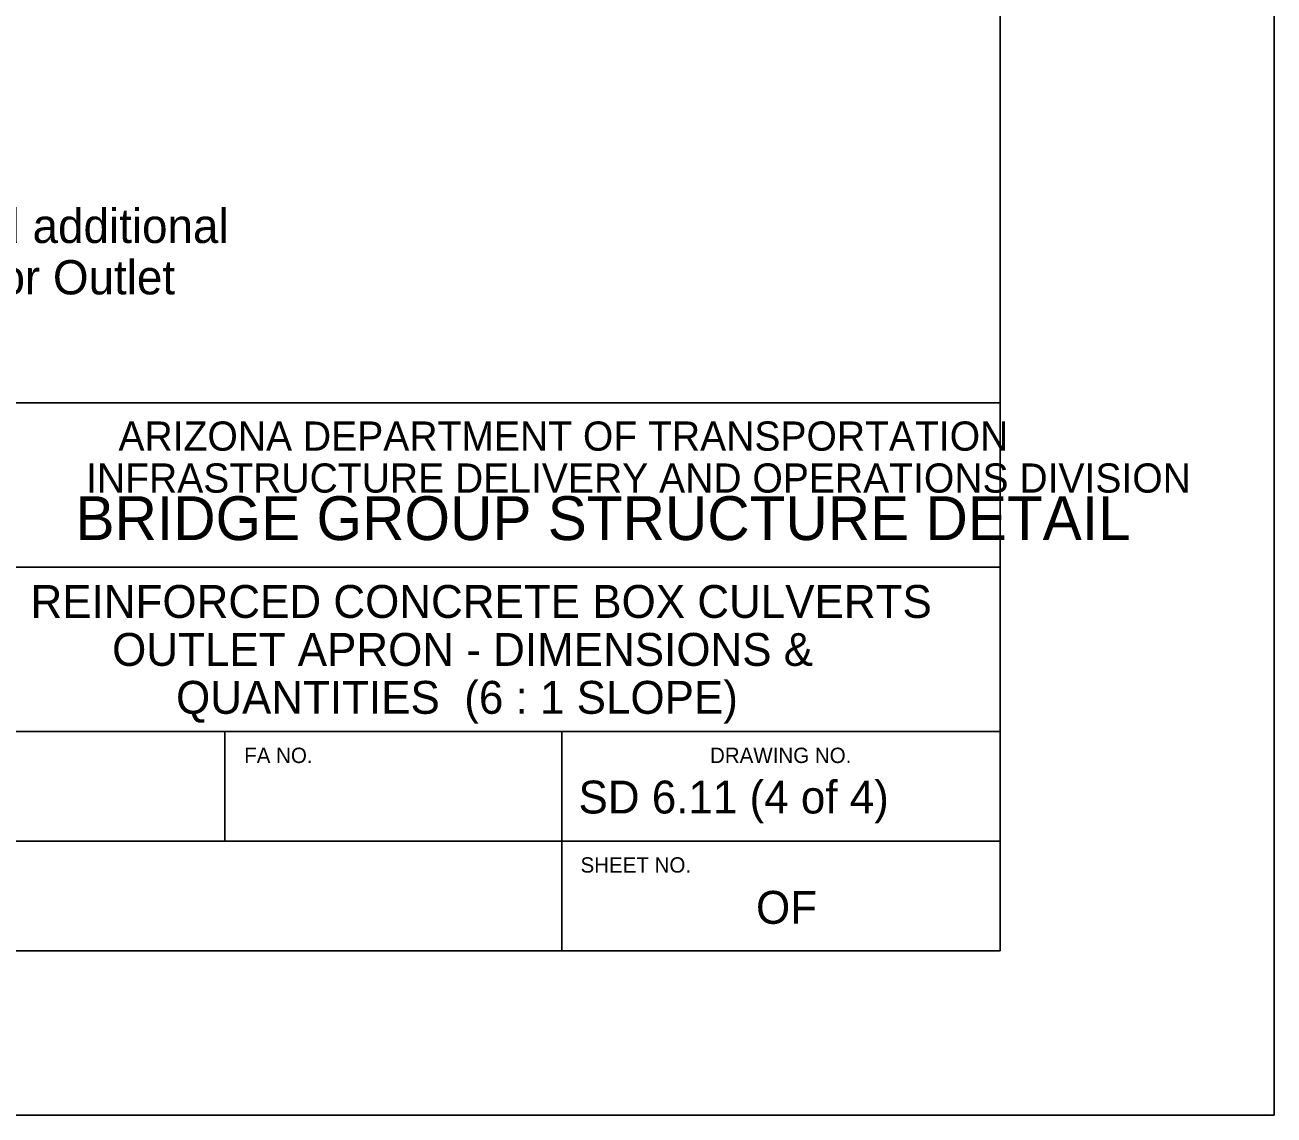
# Model space of a CAD drawing. Extents: x -0.08 to 2.83, y -0.03 to 1.92.
# Drawn here: x 2.3584 to 2.8333, y 0 to 0.4144 of the extents above; entities that cross this region are included whole.
import ezdxf

# ---------------------------------------------------------------- set-up
doc = ezdxf.new("R2010")
doc.units = 0
for name, color, linetype in [('57', 7, 'Continuous'), ('62', 7, 'Continuous'), ('63', 7, 'Continuous')]:
    doc.layers.add(name, color=color, linetype=linetype)

msp = doc.modelspace()

# ---------------------------------------------------------------- linework, layer by layer
at = {"layer": '63'}
for p, q in [((2.8333333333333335, 1.8333333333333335), (2.8333333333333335, 0)), ((2.729175, 0.270775), (2.073866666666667, 0.270775)), ((2.5728416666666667, 0.270775), (2.5728416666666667, 0.270775)), ((2.073866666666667, 0.20827500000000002), (2.729175, 0.20827500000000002)), ((2.073866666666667, 0.14577500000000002), (2.729175, 0.14577500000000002)), ((2.434346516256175, 0.10410833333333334), (2.434346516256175, 0.14577500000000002)), ((2.073866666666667, 0.10410833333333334), (2.5625083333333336, 0.10410833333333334)), ((2.5625083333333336, 0.10410833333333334), (2.5625083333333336, 0.06244166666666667)), ((2.729175, 0.06244166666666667), (2.729175, 0.10410833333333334)), ((2.073866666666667, 0.06244166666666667), (2.729175, 0.06244166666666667)), ((2.8333333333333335, 0), (0, 0)), ((2.83, 0.00032500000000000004), (2.83, 0.00032500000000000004))]:
    msp.add_line(p, q, dxfattribs=at)
msp.add_lwpolyline([(0.16667500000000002, 0.06244166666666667), (0.16667500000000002, 1.770775), (2.729175, 1.770775), (2.729175, 0.10410833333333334), (2.5625083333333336, 0.10410833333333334), (2.5625083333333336, 0.14577500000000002), (2.073866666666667, 0.14577500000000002), (2.073866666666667, 0.06244166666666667)], close=True, dxfattribs=at)

# ---------------------------------------------------------------- texts
at = {"layer": '57'}
for s, p in [('For General Notes, Dimensions, and additional', (2.073866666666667, 0.3315448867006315)), ('For General Notes, Dimensions, and additional', (2.073866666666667, 0.3315448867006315)), ('Details, see SD 6.01 (1 & 2 of 5).  For Outlet', (2.073866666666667, 0.3120136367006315)), ('Details, see SD 6.01 (1 & 2 of 5).  For Outlet', (2.073866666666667, 0.3120136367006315))]:
    msp.add_text(s, height=0.013020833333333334, dxfattribs=at).set_placement(p)
at = {"layer": '62'}
for s, p in [('REINFORCED CONCRETE BOX CULVERTS', (2.360501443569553, 0.18900416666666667)), ('OUTLET APRON - DIMENSIONS &', (2.3915262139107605, 0.170775)), ('QUANTITIES  (6 : 1 SLOPE)', (2.415845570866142, 0.15254583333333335)), ('SD 6.11 (4 of 4)', (2.568873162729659, 0.11464166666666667))]:
    msp.add_text(s, height=0.0125, dxfattribs=at).set_placement(p)
at = {"layer": '63'}
for s, height, p in [('ARIZONA DEPARTMENT OF TRANSPORTATION', 0.01110835, (2.3939416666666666, 0.2525833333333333)), ('INFRASTRUCTURE DELIVERY AND OPERATIONS DIVISION', 0.01110835, (2.381620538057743, 0.23663333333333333)), ('BRIDGE GROUP STRUCTURE DETAIL', 0.01666665, (2.377616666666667, 0.21860000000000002)), ('FA NO.', 0.0058333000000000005, (2.4417539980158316, 0.13383333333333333)), ('DRAWING NO.', 0.005833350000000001, (2.618879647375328, 0.13383333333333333)), ('SHEET NO.', 0.0058333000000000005, (2.569639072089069, 0.09216666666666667)), ('OF', 0.0125, (2.6363793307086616, 0.0727))]:
    msp.add_text(s, height=height, dxfattribs=at).set_placement(p)

doc.saveas('drawing.dxf')
